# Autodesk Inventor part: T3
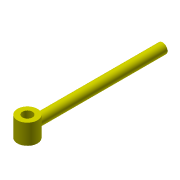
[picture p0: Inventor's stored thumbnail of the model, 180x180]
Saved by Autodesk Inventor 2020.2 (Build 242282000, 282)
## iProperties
Created: 2005-10
Part Number: T3
Document SubType Name: Modeling
Designer: F.Stasiak
Density: 1 g/cm^3
Material: Ogólny
Appearance: Żółty
Manager: www.cadconsulting.pl
Company: Fabian Stasiak CAD Consulting
Author: F.Stasiak
Subject: Zbiór ćwiczeń. Autodesk Inventor 2020. Kurs podstawowy
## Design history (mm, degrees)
sketch "Szkic1"
  geometry: L1 (0, 0)-(-10, 0); L2 (-10, 0)-(-10, -270); L3 (-10, -270)-(0, -270); L4 (0, -270)-(0, 0); C1 r 20 at (0, -270); C2 r 10 at (0, -270)
  constraints: 8 end point, 2 centre point, 2 coincident, 2 parallel, 1 horizontal, 1 perpendicular
  dimensions: "d0" = 10 distance of L2.end L3.end; "d1" = 270 distance of L3.end L1.start; "d2" = 40 diameter of C1; "d3" = 20 diameter of C2
revolve "Obrót1" stored, may be unused: angle "d4" = 90 deg
extrude "Wyciągnięcie proste1" join sketch "Szkic1" stored distance "d5" = 40; taper "d6" = 0 deg
extrude "Wyciągnięcie proste2" cut sketch "Szkic1" extent not by distance; stored distance "d7" = 120; taper "d8" = 0 deg
node "Bryła1"
node "Korpusy bryłowe"
node "Korpusy powierzchniowe"
